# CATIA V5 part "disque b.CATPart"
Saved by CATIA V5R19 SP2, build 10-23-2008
Part number: disque b
Publications: "profondeur rainure coulisseau", "hauteur du coulisseau"
Bounding box of the stored display mesh (mm): x -73 to -60, y -10 to 30, z -20 to 20
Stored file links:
  C:\Users\Thinkmotion2\Desktop\Pack 1\IAO_2010_1396_fvigouroux\vigouroux\vigouroux\disque b.CATPart
  C:\Users\Thinkmotion2\Desktop\Pack 1\IAO_2010_1396_fvigouroux\vigouroux\vigouroux\mecanisme IAO.CATProduct
  C:\Users\Thinkmotion2\Desktop\Pack 1\IAO_2010_1396_fvigouroux\vigouroux\vigouroux\coulisseau.CATPart
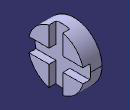
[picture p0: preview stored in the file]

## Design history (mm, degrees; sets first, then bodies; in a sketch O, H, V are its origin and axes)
Parameters
  `hauteur du coulisseau` = 5 mm
  `profondeur rainure disque` = 5 mm
External parameters (linked from other documents)
  `External.diametre arbre sortie` = 5 mm
  `External.hauteur du coulisseau` = 5 mm
Set1
  Plane1: linked copy from another document
  Point1: linked copy from another document
  Plane2: linked copy from another document
  Line1: linked copy from another document
Body1 (main body)
  Sketch1 on Plane1, origin (-60, 0, 0), H (0, 1, 0), V (0, 0, 1)
    circle A1 centre (10, 0) radius 20
    point P1 (10, 0)
    reference projected point E1 (10, 0) from Point1
    radius A1 = 20
    distance P1 E1 = 0
  Pad1: profile Sketch1, direction (-1, 0, 0), up to Plane2
  Sketch2 on start face of Pad1, origin (-60, 0, 0), H (0, 1, 0), V (0, 0, 1)
    line L1 (5, 21.5) -> (15, 21.5)
    line L2 (15, 21.5) -> (15, -21.5)
    line L3 (15, -21.5) -> (5, -21.5)
    line L4 (5, -21.5) -> (5, 21.5)
    reference projected point E1 (10, 0) from Point1
    reference projected point E2 (10, 0) from Point1
    reference projected point E3 (10, 0) from Point1
    distance E1 L2 = 5
    distance E2 L4 = 5 {= `External.hauteur du coulisseau`}
    length L2 = 43
    distance E3 L1 = 21.5
    horizontal: L1 H, L3 H
    vertical: L2 V, L4 V
  Pocket1: profile Sketch2, direction (-1, 0, 0), length 5 {= `profondeur rainure disque`}
  CircPattern1: of Pocket1, instances 2, angular step 90, axis from Line1
  Sketch3 on end face of Pad1, origin (-73, 10, 0), H (0, 1, 0), V (0, 0, -1)
    point P1 (0, 0)
  Hole1: placed by Sketch3, at (-73, 10, 0) direction (1, 0, 0), diameter 10, depth 5 {= `External.diametre arbre sortie`}
  Sketch4 on face of CircPattern1, origin (-65, 0, 0), H (0, 1, 0), V (0, 0, 1)
    circle A1 centre (10, 0) radius 20
    point P1 (10, 0)
    reference projected point E1 (10, 0) from Point1
    radius A1 = 20
    distance P1 E1 = 0
  Pad2: profile Sketch4, direction (-1, 0, 0), up to Plane2
  Sketch5 on face of Pad2, origin (-65, 0, 0), H (0, 1, 0), V (0, 0, 1)
    circle A1 centre (10, 0) radius 20
    point P1 (10, 0)
    reference projected point E1 (10, 0) from Point1
    radius A1 = 20
    distance P1 E1 = 0
  Pad3: profile Sketch5, direction (-1, 0, 0), up to Plane2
